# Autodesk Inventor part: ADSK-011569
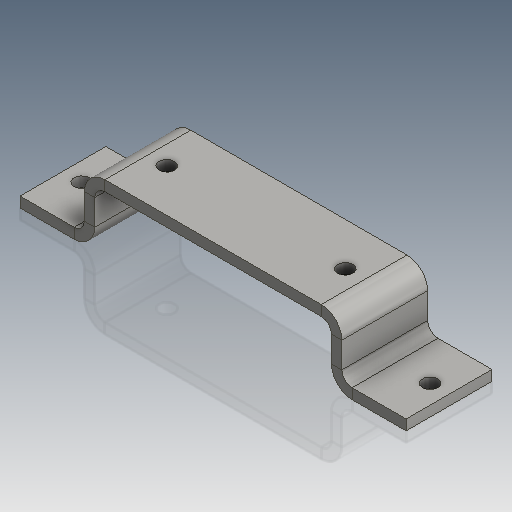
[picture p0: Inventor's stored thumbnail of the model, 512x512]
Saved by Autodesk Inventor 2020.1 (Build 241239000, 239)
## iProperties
Created: 2000-02
Part Number: ADSK-011569
Material: 1.0312 DC05
Description: FSHTPH,FH,CV,090,020,015,090,MNT,BRNG
Document SubType Name: Tôlerie
Designer: cmcgourin
Density: 1 g/cm^3
Sheet Metal Rule: Stahlblech 1.0312 - DC05 -   6.0 mm
Appearance: Stahl
Mass: 81.1378 g
Surface Area: 316.311 cm^2
Volume: 81.1378 cm^3
Sheet Metal Width: 50,000 mm
Sheet Metal Length: 273,287 mm
Sheet Metal Area: 13664,336 mm^2
Flat Pattern Width: 5 cm
Flat Pattern Length: 27.3287 cm
Flat Pattern Area: 136.643 cm^2
Control State: 0
Checked Out: False
Master: False
Shininess: 25.0
Length Units: 11269
Angle Units: 11279
Time Units: 11290
Mass Units: 11283
Length Display Precision: 3
Angle Display Precision: 2
Compacted: True
Cutlength: 10.86
Material Desc: FLAT,HRS,0.250X02.000
Material_Number: A084333
G_L: 50x273,3 mm
Thickness: 6,000 mm
Dimensions: 225x50x39 mm
Mass: 0,081 kg
Semi finished: Stahlblech 1.0312 - DC05 -   6.0 mm
VLT_Material: 1.0312 DC05
Density: 0.0
Volumn: 0.0
Area: 0.0
PropertySet Name: Model Information
Author: cmcgourin
Revision Number: -
Title: FSHTPH,FH,CV,090,020,015,090,MNT,BRNG
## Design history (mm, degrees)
node "Solide1"
  node "Konturlasche1"
  node "Hole1" dims "d11" = 9, "d12" = 9.525, "d13" = 6.35, "d14" = 60 deg, "d15" = 19.05, "d16" = 118 deg, "d43" = 6
  node "Hole2" dims "d21" = 9, "d22" = 9.525, "d23" = 6.35, "d24" = 60 deg, "d25" = 19.05, "d26" = 118 deg, "d45" = 6
sketch "Sketch1"
  geometry: L1 (33, -75)-(0, -75); L2 (0, -75)-(0, 75); L3 (0, 75)-(33, 75); L4 (33, -75)-(33, -112.5); L5 (33, 75)-(33, 112.5); 2 further points
  constraints: 10 end point, 2 equal length, 2 vertical, 1 coincident, 1 collinear, 1 horizontal, 1 midpoint, 1 perpendicular
  dimensions: "d28" = 150 distance of L1.end L2.end; "d29" = 33 distance of L2.end L3.end; "d30" = 225 distance of L4.end L5.end
feature "Grobblech1" dims "d31" = 6 (= Thickness), "d32" = 6 (= BendReliefWidth), "d33" = 3 (= BendReliefDepth), "d34" = 12 (= MinimumRemnant), "d35" = 6 (= TransitionRadius), "d36" = 50, "d37" = 6 (= BendRadius), "d38" = 3, "d39" = 24 (= CornerReliefSize), "d40" = 6 (= TailleJeu), "d41" = 6 (= TailleRayonJacobi), "SeamGap" = 0.00508
feature "Biegung1" dims "d31" = 6 (= Thickness), "d32" = 6 (= BendReliefWidth), "d33" = 3 (= BendReliefDepth), "d34" = 12 (= MinimumRemnant), "d35" = 6 (= TransitionRadius), "d37" = 6 (= BendRadius), "d38" = 3, "SeamGap" = 0.00508
feature "Ecke1" dims "d38" = 3, "d39" = 24 (= CornerReliefSize), "d40" = 6 (= TailleJeu), "d41" = 6 (= TailleRayonJacobi)
sketch "Sketch3"
  geometry: L1 (50.8, 682.679)-(50.8, 786.679); L2 (25.8, 671.679)-(25.8, 797.679) reference; 5 further points
  constraints: 3 coincident, 2 end point, 2 midpoint, 1 horizontal alignment, 1 vertical
  dimensions: "d44" = 104 distance of L1.start L1.end
node "Corps solides"
node "Corps surfaciques"
sketch "Sketch2"
  geometry: L1 (0, 588.729)-(0, 791.729); 2 further points
  constraints: 2 end point, 1 coincident, 1 midpoint, 1 vertical
  dimensions: "d42" = 203 distance of L1.start L1.end
feature "Definition1"
other parameters: "Thickness" = 6 (derived), "BendRadius" = 6 (= Thickness), "BendReliefWidth" = 6 (= Thickness), "BendReliefDepth" = 3 (= 0.5 x Thickness), "CornerReliefSize" = 24 (= 4 x Thickness), "MinimumRemnant" = 12 (= 2 x Thickness), "TransitionRadius" = 6 (= BendRadius), "TailleRayonJacobi" = 6 (= BendRadius), "TailleJeu" = 6 (= Thickness), "BendRadius" = 6, "BendReliefDepth" = 3, "BendReliefWidth" = 6, "CornerReliefSize" = 24, "MinimumRemnant" = 12, "TailleJeu" = 6, "TailleRayonJacobi" = 6, "Thickness" = 6, "TransitionRadius" = 6
